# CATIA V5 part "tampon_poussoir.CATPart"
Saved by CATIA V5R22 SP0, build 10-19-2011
Part number: tampon_poussoir
Bounding box of the stored display mesh (mm): x 0 to 10, y 0 to 35, z 0 to 35
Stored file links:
  C:\Users\La forge\Desktop\CAO_PER_pick&place_2023A\Sous_Ensemble_Flacon\Verin\Poussoir_Flacon\tampon_poussoir.CATPart
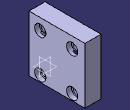
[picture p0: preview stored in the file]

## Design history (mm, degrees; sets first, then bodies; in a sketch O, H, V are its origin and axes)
Body1 (main body)
  Sketch1 on yz-plane, origin (0, 0, 0), H (0, 1, 0), V (0, 0, 1)
    line L1 (0, 0) -> (35, 0)
    line L2 (35, 0) -> (35, 35)
    line L3 (35, 35) -> (0, 35)
    line L4 (0, 35) -> (0, 0)
    point P1 (35, 0)
    point P2 (35, 35)
    length L3 = 35
    distance P1 P2 = 35
    horizontal: L1 H, L3 H
    vertical: L2 V, L4 V
  Pad1: profile Sketch1, direction (1, 0, 0), length 10
  Sketch2 on end face of Pad1, origin (10, 9.1342, 17.2687), H (0, 1, 0), V (0, 0, 1)
    point P1 (-2.1342, 10.7313)
    reference projected line E1 (-9.1342, 17.7313) -> (-9.1342, -17.2687) from edge [face of Pad1 from Sketch1.L4 | end face of Pad1]
    reference projected line E2 (25.8658, 17.7313) -> (-9.1342, 17.7313) from edge [face of Pad1 from Sketch1.L3 | end face of Pad1]
    distance P1 E1 = 7
    distance P1 E2 = 7
  Hole1: placed by Sketch2, at (10, 7, 28) direction (-1, 0, 0), diameter 5, through (limit type 3), counterbore diameter 7, counterbore depth 3
  RectPattern1: of Hole1, direction 1 instances 2, spacing 20, along end face of Pad1, direction 2 instances 2, spacing 24, along end face of Pad1 reversed
  Sketch3 on start face of Pad1, origin (0, 0, 0), H (0, -1, 0), V (0, 0, 1)
    line L1 (-5, 7.5) -> (-30, 7.5)
    line L2 (-30, 7.5) -> (-30, 25)
    line L3 (-30, 25) -> (-5, 25)
    line L4 (-5, 25) -> (-5, 7.5)
    reference projected line E1 (0, 35) -> (0, 0) from edge [start face of Pad1 | face of Pad1 from Sketch1.L4]
    reference projected line E2 (-35, 35) -> (0, 35) from edge [start face of Pad1 | face of Pad1 from Sketch1.L3]
    reference projected line E3 (-35, 0) -> (-35, 35) from edge [start face of Pad1 | face of Pad1 from Sketch1.L2]
    reference projected line E4 (0, 0) -> (-35, 0) from edge [start face of Pad1 | face of Pad1 from Sketch1.L1]
    distance L4 E1 = 5
    distance L3 E2 = 10
    distance L2 E3 = 5
    distance L1 E4 = 7.5
    horizontal: L1 H, L3 H
    vertical: L2 V, L4 V
  Pocket1: profile Sketch3, direction (1, 0, 0), length 8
